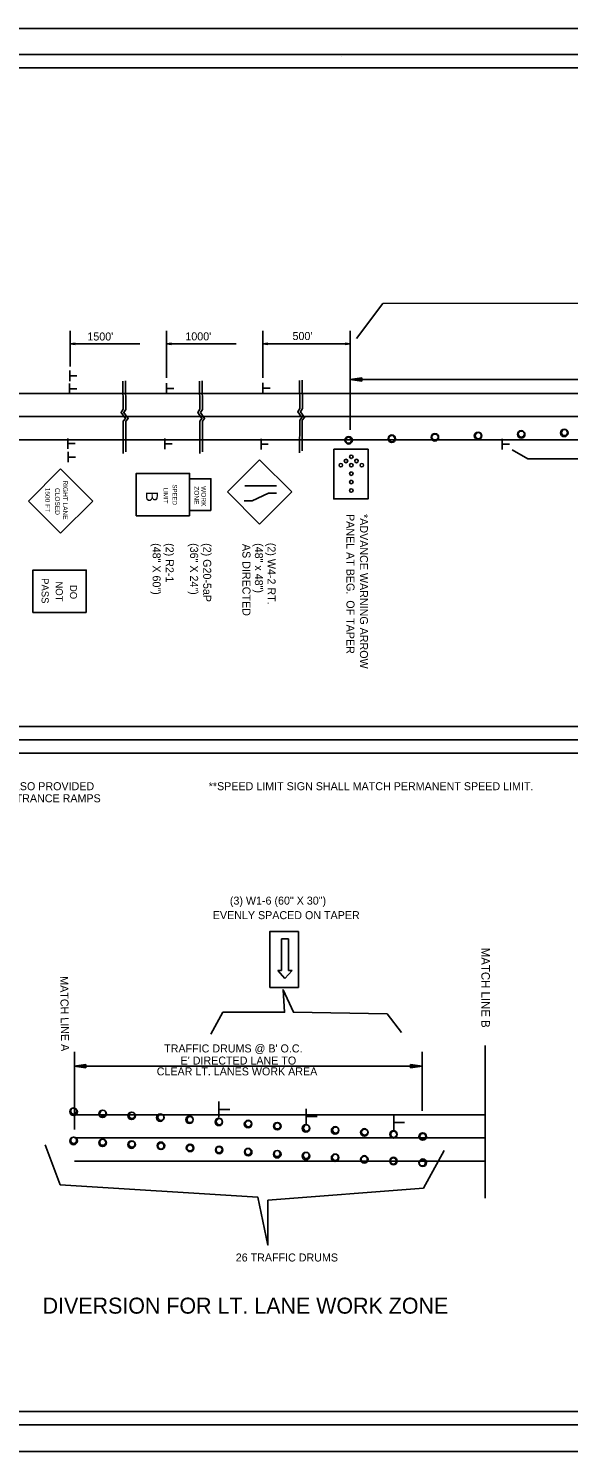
# Model space of a CAD drawing. Extents: x 1373222 to 1374279, y 380783 to 380996.
# Drawn here: x 1373701.6 to 1373782.6, y 380783.1 to 380996.5 of the extents above; entities that cross this region are included whole.
import ezdxf

# ---------------------------------------------------------------- set-up
doc = ezdxf.new("R2010")
doc.units = 0
for name, color, linetype in [('Default', 7, 'Continuous'), ('R_Border', 7, 'Continuous'), ('R_Border Plan-Plan', 7, 'Continuous'), ('R_Draft', 7, 'Continuous'), ('R_No Plot', 7, 'Continuous')]:
    doc.layers.add(name, color=color, linetype=linetype)

msp = doc.modelspace()

# ---------------------------------------------------------------- linework, layer by layer
at = {"layer": 'Default'}
for p, q in [((1373707.9, 380951.16), (1373707.9, 380945.79)), ((1373722.33, 380951.16), (1373722.33, 380944.12)), ((1373736.77, 380951.16), (1373736.77, 380944.12)), ((1373749.86, 380951.16), (1373749.86, 380936.34)), ((1373708.65, 380949.32), (1373707.9, 380949.21)), ((1373707.9, 380949.21), (1373718.34, 380949.21)), ((1373708.65, 380949.09), (1373707.9, 380949.21)), ((1373708.65, 380949.3), (1373708.02, 380949.21)), ((1373708.65, 380949.11), (1373708.02, 380949.21)), ((1373708.65, 380949.28), (1373708.15, 380949.21)), ((1373708.65, 380949.13), (1373708.15, 380949.21)), ((1373708.65, 380949.26), (1373708.28, 380949.21)), ((1373708.65, 380949.15), (1373708.28, 380949.21)), ((1373708.65, 380949.24), (1373708.41, 380949.21)), ((1373708.65, 380949.17), (1373708.41, 380949.21)), ((1373708.65, 380949.22), (1373708.53, 380949.21)), ((1373708.65, 380949.19), (1373708.53, 380949.21)), ((1373708.65, 380949.09), (1373708.65, 380949.32)), ((1373723.08, 380949.32), (1373722.33, 380949.21)), ((1373722.33, 380949.21), (1373732.77, 380949.21)), ((1373723.08, 380949.09), (1373722.33, 380949.21)), ((1373723.08, 380949.3), (1373722.46, 380949.21)), ((1373723.08, 380949.11), (1373722.46, 380949.21)), ((1373723.08, 380949.28), (1373722.59, 380949.21)), ((1373723.08, 380949.13), (1373722.59, 380949.21)), ((1373723.08, 380949.26), (1373722.71, 380949.21)), ((1373723.08, 380949.15), (1373722.71, 380949.21)), ((1373723.08, 380949.24), (1373722.84, 380949.21)), ((1373723.08, 380949.17), (1373722.84, 380949.21)), ((1373723.08, 380949.22), (1373722.96, 380949.21)), ((1373723.08, 380949.19), (1373722.96, 380949.21)), ((1373723.08, 380949.09), (1373723.08, 380949.32)), ((1373737.52, 380949.32), (1373736.77, 380949.21)), ((1373736.77, 380949.21), (1373749.86, 380949.21)), ((1373737.52, 380949.09), (1373736.77, 380949.21)), ((1373737.52, 380949.3), (1373736.89, 380949.21)), ((1373737.52, 380949.11), (1373736.89, 380949.21)), ((1373737.52, 380949.28), (1373737.02, 380949.21)), ((1373737.52, 380949.13), (1373737.02, 380949.21)), ((1373737.52, 380949.26), (1373737.14, 380949.21)), ((1373737.52, 380949.15), (1373737.14, 380949.21)), ((1373737.52, 380949.24), (1373737.27, 380949.21)), ((1373737.52, 380949.17), (1373737.27, 380949.21)), ((1373737.52, 380949.22), (1373737.4, 380949.21)), ((1373737.52, 380949.19), (1373737.4, 380949.21)), ((1373737.52, 380949.09), (1373737.52, 380949.32)), ((1373749.11, 380949.32), (1373749.86, 380949.21)), ((1373749.11, 380949.32), (1373749.11, 380949.09)), ((1373749.11, 380949.3), (1373749.73, 380949.21)), ((1373749.11, 380949.28), (1373749.61, 380949.21)), ((1373749.11, 380949.26), (1373749.48, 380949.21)), ((1373749.11, 380949.24), (1373749.35, 380949.21)), ((1373749.11, 380949.22), (1373749.23, 380949.21)), ((1373749.11, 380949.09), (1373749.86, 380949.21)), ((1373749.11, 380949.17), (1373749.35, 380949.21)), ((1373749.11, 380949.13), (1373749.61, 380949.21)), ((1373749.11, 380949.11), (1373749.73, 380949.21)), ((1373749.11, 380949.15), (1373749.48, 380949.21)), ((1373749.11, 380949.19), (1373749.23, 380949.21)), ((1373749.86, 380946.6), (1373749.86, 380939.56)), ((1373707.83, 380943.62), (1373707.83, 380945.19)), ((1373707.85, 380944.4), (1373708.92, 380944.4)), ((1373707.82, 380941.69), (1373707.82, 380943.25)), ((1373707.85, 380942.47), (1373708.91, 380942.47)), ((1373722.33, 380941.73), (1373722.33, 380943.3)), ((1373722.36, 380942.51), (1373723.42, 380942.51)), ((1373736.77, 380941.77), (1373736.77, 380943.34)), ((1373736.79, 380942.55), (1373737.86, 380942.55)), ((1373749.86, 380943.86), (1373751.6, 380944.12)), ((1373840.26, 380943.86), (1373749.86, 380943.86)), ((1373751.6, 380943.6), (1373749.86, 380943.86)), ((1373751.6, 380944.12), (1373751.6, 380943.6)), ((1373608.96, 380941.78), (1373892.42, 380941.78)), ((1373608.96, 380938.31), (1373892.42, 380938.31)), ((1373608.96, 380934.83), (1373892.42, 380934.83)), ((1373707.57, 380933.48), (1373707.57, 380935.04)), ((1373707.59, 380934.25), (1373708.66, 380934.25)), ((1373722.08, 380933.43), (1373722.08, 380935)), ((1373722.1, 380934.21), (1373723.17, 380934.21)), ((1373736.51, 380933.39), (1373736.51, 380934.96)), ((1373736.54, 380934.17), (1373737.6, 380934.17)), ((1373772.67, 380933.38), (1373772.67, 380934.95)), ((1373772.69, 380934.16), (1373773.76, 380934.16)), ((1373707.59, 380931.47), (1373707.59, 380933.03)), ((1373707.61, 380932.24), (1373708.68, 380932.24)), ((1373736.3, 380931.82), (1373731.48, 380927)), ((1373736.3, 380931.82), (1373741.12, 380927)), ((1373701.65, 380925.63), (1373706.46, 380930.45)), ((1373711.27, 380925.64), (1373706.46, 380930.45)), ((1373734.07, 380927.93), (1373738.81, 380927.93)), ((1373706.47, 380920.82), (1373701.65, 380925.63)), ((1373706.47, 380920.82), (1373711.27, 380925.64)), ((1373731.48, 380927), (1373736.3, 380922.18)), ((1373733.97, 380925.68), (1373735.19, 380925.68)), ((1373735.19, 380925.68), (1373737.64, 380926.8)), ((1373741.12, 380927), (1373736.3, 380922.18)), ((1373737.64, 380926.8), (1373738.81, 380926.8)), ((1373739.57, 380860.03), (1373739.57, 380855.25)), ((1373739.57, 380860.03), (1373740.64, 380860.03)), ((1373740.64, 380860.03), (1373740.64, 380855.25)), ((1373739.57, 380855.25), (1373739.04, 380855.25)), ((1373739.04, 380855.25), (1373740.1, 380854.08)), ((1373740.1, 380854.08), (1373741.17, 380855.25)), ((1373740.64, 380855.25), (1373741.17, 380855.25)), ((1373770.1, 380844.02), (1373770.1, 380821.11)), ((1373708.53, 380843.07), (1373708.53, 380831.41)), ((1373760.65, 380843.07), (1373760.65, 380834.21)), ((1373770.1, 380842.16), (1373770.1, 380831.95)), ((1373708.49, 380840.91), (1373710.23, 380841.17)), ((1373760.65, 380840.91), (1373708.49, 380840.91)), ((1373710.23, 380840.65), (1373708.49, 380840.91)), ((1373708.53, 380840.02), (1373708.53, 380831.41)), ((1373710.23, 380841.17), (1373710.23, 380840.65)), ((1373758.91, 380840.65), (1373758.91, 380841.17)), ((1373758.91, 380841.17), (1373760.65, 380840.91)), ((1373760.65, 380840.91), (1373758.91, 380840.65)), ((1373730.21, 380833.3), (1373730.21, 380835.62)), ((1373708.53, 380833.64), (1373762.34, 380833.64)), ((1373730.24, 380834.45), (1373731.83, 380834.45)), ((1373743.29, 380832.21), (1373743.29, 380834.54)), ((1373743.33, 380833.37), (1373744.91, 380833.37)), ((1373756.41, 380831.31), (1373756.41, 380833.63)), ((1373760.68, 380833.64), (1373770.1, 380833.64)), ((1373756.44, 380832.47), (1373758.02, 380832.47)), ((1373708.53, 380830.16), (1373770.1, 380830.16)), ((1373708.53, 380826.68), (1373763.78, 380826.68)), ((1373760.6, 380826.68), (1373770.1, 380826.68))]:
    msp.add_line(p, q, dxfattribs=at)
for points in [[(1373750.83, 380950.03), (1373754.78, 380955.27), (1373838.44, 380955.36), (1373840.05, 380960.2), (1373840.19, 380955.43), (1373889.53, 380954.77), (1373891.81, 380949.57)], [(1373715.79, 380943.6), (1373715.86, 380939.39), (1373715.53, 380938.91), (1373716.17, 380938.04), (1373715.83, 380937.64), (1373715.83, 380932.75)], [(1373716.19, 380943.64), (1373716.26, 380939.37), (1373715.93, 380938.89), (1373716.57, 380938.02), (1373716.23, 380937.62), (1373716.23, 380933.03)], [(1373727.29, 380943.6), (1373727.35, 380939.39), (1373727.03, 380938.91), (1373727.66, 380938.04), (1373727.33, 380937.64), (1373727.32, 380932.75)], [(1373727.69, 380943.64), (1373727.75, 380939.37), (1373727.43, 380938.89), (1373728.06, 380938.02), (1373727.72, 380937.62), (1373727.72, 380933.03)], [(1373742.27, 380943.72), (1373742.33, 380939.52), (1373742.01, 380939.03), (1373742.64, 380938.17), (1373742.31, 380937.77), (1373742.3, 380932.88)], [(1373742.67, 380943.76), (1373742.73, 380939.5), (1373742.41, 380939.02), (1373743.04, 380938.15), (1373742.7, 380937.75), (1373742.7, 380933.16)], [(1373774.17, 380933.34), (1373776.49, 380931.98), (1373792.02, 380931.98), (1373792.15, 380930.34), (1373792.7, 380931.84), (1373814.9, 380931.71), (1373817.49, 380934.02)], [(1373729, 380845.74), (1373730.8, 380849.01), (1373740.05, 380849.01), (1373739.81, 380852.38), (1373741.37, 380849.01), (1373755.42, 380848.77), (1373757.58, 380845.98)], [(1373704.17, 380829.14), (1373706.42, 380823.15), (1373736.04, 380821.26), (1373737.55, 380814.11), (1373737.55, 380820.82), (1373760.85, 380822.63), (1373763.95, 380828.29)]]:
    msp.add_lwpolyline(points, dxfattribs=at)
for points in [[(1373747.41, 380933.4), (1373747.41, 380925.95), (1373752.56, 380925.95), (1373752.56, 380933.4)], [(1373725.79, 380923.44), (1373717.8, 380923.44), (1373717.8, 380929.78), (1373725.79, 380929.78)], [(1373728.99, 380924.24), (1373725.79, 380924.24), (1373725.79, 380928.99), (1373728.99, 380928.99)], [(1373710.31, 380908.95), (1373702.32, 380908.95), (1373702.32, 380915.29), (1373710.31, 380915.29)], [(1373737.82, 380852.72), (1373737.82, 380861.1), (1373742.11, 380861.1), (1373742.11, 380852.72)]]:
    msp.add_lwpolyline(points, close=True, dxfattribs=at)
for centre, radius in [((1373708.41, 380834.09), 0.563), ((1373708.41, 380834.18), 0.458), ((1373708.44, 380834.18), 0.458), ((1373712.76, 380833.78), 0.563), ((1373712.8, 380833.86), 0.458), ((1373717.11, 380833.48), 0.563), ((1373717.16, 380833.55), 0.458), ((1373721.4, 380833.2), 0.563), ((1373721.52, 380833.23), 0.458), ((1373725.79, 380832.89), 0.563), ((1373725.88, 380832.92), 0.458), ((1373730.18, 380832.57), 0.563), ((1373730.24, 380832.6), 0.458), ((1373734.57, 380832.25), 0.563), ((1373734.61, 380832.29), 0.458), ((1373738.95, 380831.93), 0.563), ((1373738.97, 380831.97), 0.458), ((1373743.25, 380831.6), 0.563), ((1373743.33, 380831.66), 0.458), ((1373747.62, 380831.29), 0.563), ((1373747.69, 380831.34), 0.458), ((1373752, 380830.99), 0.563), ((1373752.05, 380831.03), 0.458), ((1373756.37, 380830.69), 0.563), ((1373756.41, 380830.71), 0.458), ((1373708.41, 380829.71), 0.563), ((1373708.41, 380829.8), 0.458), ((1373708.44, 380829.8), 0.458), ((1373712.76, 380829.43), 0.563), ((1373712.79, 380829.52), 0.458), ((1373717.11, 380829.16), 0.563), ((1373717.15, 380829.23), 0.458), ((1373721.51, 380828.99), 0.563), ((1373721.5, 380828.95), 0.458), ((1373725.87, 380828.67), 0.563), ((1373725.86, 380828.67), 0.458), ((1373760.75, 380830.38), 0.563), ((1373760.75, 380830.4), 0.458), ((1373760.77, 380830.39), 0.458), ((1373730.23, 380828.36), 0.563), ((1373730.22, 380828.39), 0.458), ((1373734.59, 380828.04), 0.563), ((1373734.57, 380828.11), 0.458), ((1373738.95, 380827.72), 0.563), ((1373738.93, 380827.82), 0.458), ((1373743.25, 380827.44), 0.563), ((1373743.28, 380827.54), 0.458), ((1373747.62, 380827.19), 0.563), ((1373747.64, 380827.26), 0.458), ((1373752, 380826.95), 0.563), ((1373751.99, 380826.98), 0.458), ((1373756.37, 380826.7), 0.563), ((1373756.35, 380826.7), 0.458), ((1373760.75, 380826.45), 0.563), ((1373760.68, 380826.42), 0.458), ((1373760.7, 380826.41), 0.458)]:
    msp.add_circle(centre, radius, dxfattribs=at)
for centre, major_axis in [((1373762.58, 380935.2), (0, 0.563)), ((1373762.59, 380935.22), (0, 0.458)), ((1373769.05, 380935.42), (0, 0.563)), ((1373769.07, 380935.45), (0, 0.458)), ((1373775.52, 380935.64), (0, 0.563)), ((1373775.54, 380935.68), (0, 0.458)), ((1373781.98, 380935.86), (0, 0.563)), ((1373782.01, 380935.91), (0, 0.458)), ((1373749.65, 380934.75), (0, 0.563)), ((1373749.62, 380934.76), (0, 0.458)), ((1373749.65, 380934.76), (0, 0.458)), ((1373756.12, 380934.98), (0, 0.563)), ((1373756.12, 380934.99), (0, 0.458)), ((1373749.25, 380931.65), (0, 0.262)), ((1373750.04, 380932.28), (0, 0.262)), ((1373750.83, 380931.65), (0, 0.262)), ((1373748.47, 380931.02), (0, 0.262)), ((1373750.04, 380931.02), (0, 0.262)), ((1373750.04, 380929.75), (0, 0.262)), ((1373751.62, 380931.02), (0, 0.262)), ((1373750.04, 380928.49), (0, 0.262)), ((1373750.04, 380927.22), (0, 0.262))]:
    msp.add_ellipse(centre, major_axis=major_axis, ratio=0.99998, dxfattribs=at)
at = {"layer": 'R_Border'}
for p, q in [((1373596.1, 380992.59), (1373912.28, 380992.59)), ((1373748.62, 380992.33), (1373748.62, 380992.33)), ((1373748.62, 380992.33), (1373748.62, 380992.33)), ((1373912.28, 380787.13), (1373596.1, 380787.13))]:
    msp.add_line(p, q, dxfattribs=at)
at = {"layer": 'R_Border Plan-Plan'}
msp.add_line((1373596.1, 380889.86), (1373912.28, 380889.86), dxfattribs=at)
at = {"layer": 'R_No Plot'}
for points in [[(1373583.69, 380996.49), (1373917.03, 380996.49), (1373917.03, 380783.15), (1373583.69, 380783.15)], [(1373910.28, 380891.86), (1373598.1, 380891.86), (1373598.1, 380990.59), (1373847.64, 380990.59), (1373847.64, 380980.71), (1373865.18, 380980.71), (1373889.28, 380980.71), (1373889.28, 380958.38), (1373910.28, 380958.38)], [(1373598.1, 380990.59), (1373847.64, 380990.59), (1373847.64, 380980.71), (1373865.18, 380980.71), (1373889.28, 380980.71), (1373889.28, 380958.38), (1373910.28, 380958.38), (1373910.28, 380789.13), (1373598.1, 380789.13)], [(1373598.1, 380887.86), (1373910.28, 380887.86), (1373910.28, 380789.13), (1373598.1, 380789.13)]]:
    msp.add_lwpolyline(points, close=True, dxfattribs=at)

# ---------------------------------------------------------------- texts
at = {"layer": 'Default'}
for s, height, p in [("1500'", 1.2, (1373710.48, 380949.71)), ("1000'", 1.2, (1373725.17, 380949.73)), ("500'", 1.2, (1373741.23, 380949.78)), ('SPEED LIMIT SIGNS ARE ALSO PROVIDED', 1.2, (1373678.77, 380882.29)), ('**SPEED LIMIT SIGN SHALL MATCH PERMANENT SPEED LIMIT.', 1.2, (1373728.67, 380882.29)), ('FOR PLACEMENT PAST ENTRANCE RAMPS ', 1.2, (1373678.77, 380880.48)), ("TRAFFIC DRUMS @ B' O.C.", 1.2, (1373721.99, 380842.98)), ("E' DIRECTED LANE TO", 1.2, (1373724.45, 380841.16)), ('CLEAR LT. LANES WORK AREA', 1.2, (1373720.87, 380839.54)), ('26 TRAFFIC DRUMS', 1.2, (1373732.72, 380811.64)), ('DIVERSION FOR LT. LANE WORK ZONE', 2.4, (1373703.77, 380803.82))]:
    msp.add_text(s, height=height, dxfattribs=at).set_placement(p)
for s, height, rotation, p in [('1500 FT', 0.713, 270.0006, (1373704.17, 380927.64)), ('CLOSED', 0.709, 270.1003, (1373705.63, 380927.59)), ('RIGHT LANE', 0.709, 270.1004, (1373706.81, 380928.73)), ('LIMIT', 0.661, 270, (1373721.89, 380927.63)), ('SPEED', 0.661, 270, (1373723.25, 380928.13)), ('ZONE', 0.709, 270.1004, (1373726.5, 380927.85)), ('WORK', 0.709, 270.1004, (1373727.56, 380927.88)), ('B', 1.77, 270, (1373719.27, 380927.09)), ('PANEL AT BEG.  OF TAPER', 1.2, 270, (1373749.32, 380923.69)), ('*ADVANCE WARNING ARROW', 1.2, 270, (1373751.34, 380923.69)), ('(48" X 60")', 1.2, 270, (1373720.26, 380919.33)), ('(2) R2-1', 1.2, 270, (1373722.22, 380919.33)), ('(36" X 24")', 1.2, 270, (1373725.88, 380919.33)), ('(2) G20-5aP', 1.2, 270, (1373727.84, 380919.33)), ('AS DIRECTED ', 1.2, 270, (1373733.73, 380919.21)), ('(48" x 48")', 1.2, 270, (1373735.59, 380919.33)), ('(2) W4-2 RT.', 1.2, 270, (1373737.49, 380919.38)), ('PASS', 1.064, 270, (1373703.61, 380914.08)), ('NOT', 1.064, 270, (1373705.73, 380913.59)), ('DO', 1.064, 270, (1373707.86, 380913.07)), ('(3) W1-6 (60" X 30")', 1.2, 0.0075, (1373731.84, 380865.14)), ('EVENLY SPACED ON TAPER', 1.2, 0.0075, (1373729.28, 380862.96)), ('MATCH LINE A', 1.2, 270.8059, (1373706.39, 380854.39))]:
    msp.add_text(s, height=height, rotation=rotation, dxfattribs=at).set_placement(p)
at = {"layer": 'R_Draft'}
msp.add_text('MATCH LINE B', height=1.28, rotation=270, dxfattribs=at).set_placement((1373769.54, 380858.67))

doc.saveas('drawing.dxf')
